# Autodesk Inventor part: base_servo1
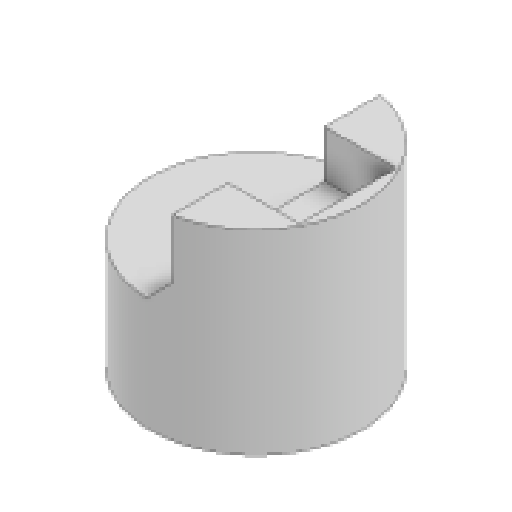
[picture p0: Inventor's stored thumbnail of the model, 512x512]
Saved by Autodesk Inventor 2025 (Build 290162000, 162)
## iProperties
Created: 2025-05
Part Number: base_servo1
Material: Plastica ABS
Document SubType Name: Modeling
Designer: R5800u
Density: 1.06 g/cm^3
Appearance: Liscia - Rosso
Author: R5800u
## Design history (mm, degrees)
sketch "Schizzo1"
  geometry: C1 r 45 at (0, 0); 1 further point
  constraints: 1 centre point, 1 coincident
  dimensions: "d0" = 90 diameter of C1
extrude "Estrusione1" new body sketch "Schizzo1" distance "d1" = 48; taper "d2" = 0 deg
sketch "Schizzo2"
  geometry: L1 (8.672, -44.156)-(8.672, 44.156); A1 r 45 centre (0, 0) between (8.672, -44.156) and (8.672, 44.156) reference; A2 r 45 centre (0, 0) between (8.672, -44.156) and (8.672, 44.156) reference; 1 further point
  constraints: 2 end point, 2 point on circle, 1 vertical
extrude "Estrusione2" join sketch "Schizzo2" distance "d3" = 35; taper "d4" = 0 deg
chamfer "Smusso1" distance "d5" = 10; stored, may be unused: second distance "d6" = 2, angle "d7" = 45 deg
sketch "Schizzo3"
  geometry: L1 (12.022, 20.1)-(32.022, 20.1) reference; L2 (32.022, -20)-(12.022, -20) reference; L3 (37.022, 16.1)-(37.022, -16) reference; L4 (8.672, 44.156)-(8.672, -44.156) reference; L5 (8.672, 20.6)-(39.022, 20.6); L6 (39.022, 20.6)-(39.022, -20.5); L7 (39.022, -20.5)-(8.672, -20.5); L8 (8.672, -20.5)-(8.672, 20.6); 2 further points
  constraints: 8 end point, 2 parallel, 1 horizontal, 1 perpendicular, 1 point on line
  dimensions: "d8" = 0.5 distance between parallel lines of L1 L5; "d9" = 0.5 distance between parallel lines of L2 L7; "d10" = 2 distance between parallel lines of L3 L6
  node "Riferimento1"
  node "Riferimento2"
  node "Riferimento3"
node "Piano di lavoro1"
extrude "Estrusione3" cut sketch "Schizzo3" stored distance "d11" = 48; taper "d12" = 0 deg
sketch "Schizzo4"
  geometry: L1 (0, 0)-(20.075, 28.67); L2 (0, 0)-(35, 0); L3 (0, 0)-(34.549, 0); L4 (0, 0)-(20.075, -28.67); L5 (0, 0)-(0, 35); L6 (0, 0)-(-20.075, 28.67); L7 (0, 0)-(-20.075, -28.67); A1 r 35 centre (0, 0) between (20.075, 28.67) and (0, 35); 1 further point
  constraints: 14 end point, 3 symmetric about line, 2 point on circle, 1 centre point, 1 coincident, 1 equal length, 1 horizontal, 1 point on line
  dimensions: "d16" = 70 diameter of A1; "d17" = 55 deg angle of L2 L1
hole "Foro1" sketch "Schizzo4" at (20.075, 28.67), (-20.075, 28.67), (-20.075, -28.67), (20.075, -28.67) diameter "d18" = 4.3; stored, may be unused: countersink angle "d22" = 90 deg, drill point angle "d24" = 118 deg; dims "d19" = 6, "d20" = 13, "d21" = 3.4, "d23" = 8
sketch "Schizzo5"
  geometry: C1 r 2.15 at (20.075, 28.67) reference; C2 r 2.15 at (20.075, -28.67) reference; 3 further points
  constraints: 2 coincident
hole "Foro2" sketch "Schizzo5" at (20.075, 28.67), (20.075, -28.67) diameter "d25" = 4.3; stored, may be unused: countersink angle "d29" = 90 deg, drill point angle "d31" = 118 deg; dims "d26" = 6, "d27" = 8, "d28" = 55, "d30" = 8
sketch "Schizzo6"
  geometry: C1 r 2.15 at (-20.075, 28.67) reference; C2 r 2.15 at (-20.075, -28.67) reference; 3 further points
  constraints: 2 coincident
hole "Foro3" sketch "Schizzo6" at (-20.075, 28.67), (-20.075, -28.67) diameter "d32" = 4.3; stored, may be unused: countersink angle "d36" = 90 deg, drill point angle "d38" = 118 deg; dims "d33" = 6, "d34" = 8, "d35" = 20, "d37" = 8
chamfer "Smusso3" distance "d39" = 5; stored, may be unused: second distance "d40" = 2, angle "d41" = 45 deg
sketch "Schizzo7"
  geometry: L1 (39.022, 20.6)-(8.672, 20.6) reference; L2 (29.898, 20.6)-(42.27, 20.6); L3 (42.27, 20.6)-(42.27, 35.587); L4 (42.27, 35.587)-(29.898, 35.587); L5 (29.898, 35.587)-(29.898, 20.6); 2 further points
  constraints: 8 end point, 2 parallel, 1 horizontal, 1 perpendicular, 1 point on line
extrude "Estrusione4" cut sketch "Schizzo7" distance "d42" = 20; taper "d43" = 0 deg
chamfer "Smusso4" distance "d44" = 2; stored, may be unused: second distance "d45" = 2, angle "d46" = 45 deg
node "Solido1"
